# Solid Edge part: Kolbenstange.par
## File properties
Author: ahadarics
Last saved by: ahadarics
Revision: 77
Sűrűség: 0,000 kg/m^3
Pontosság: 0,990
Username: ahadarics
Dokumentum tartalom típus: 0
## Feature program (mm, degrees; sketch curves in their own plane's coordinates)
base feature "unnamed BaseFeature 1"
sketch for "unnamed Protrusion 1" plane through (63.5, 0, 0) normal (1, 0, 0) x-axis (0, 1, 0)
  circle centre (0, 0) radius 12.5
extrude "unnamed Protrusion 1" add finite 33 along -normal
thread "Menet_1"  ThreadDepth = 22 mm
chamfer "Letörés_1" setback 0.7
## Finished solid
Body 1: solid body, 13 faces, 23 edges, 12 vertices.
  Faces by surface: plane 9, cylinder 3, cone 1
  Edges by curve: line 12, circle 11
Bounding box of the edges (mm): 125.500 x 25.000 x 25.000, from (-62, -12.5, -12.5) to (63.5, 12.5, 12.5).
Cylindrical faces by radius (mm): R5 x2, R12.5 x1
Conical faces (half-angle, radius in mm at the cone's reference point): 45 deg R4.3 x1
Planar faces by outward normal: +x 3, +z 1, -x 4, -z 1
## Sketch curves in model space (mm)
circle centre (63.5, 0, 0) radius 12.5
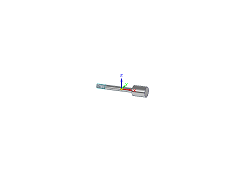
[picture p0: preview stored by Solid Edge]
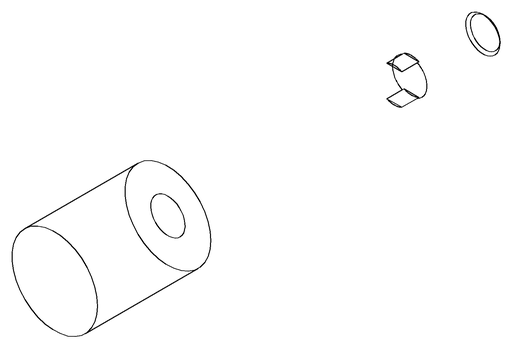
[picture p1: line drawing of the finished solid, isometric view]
